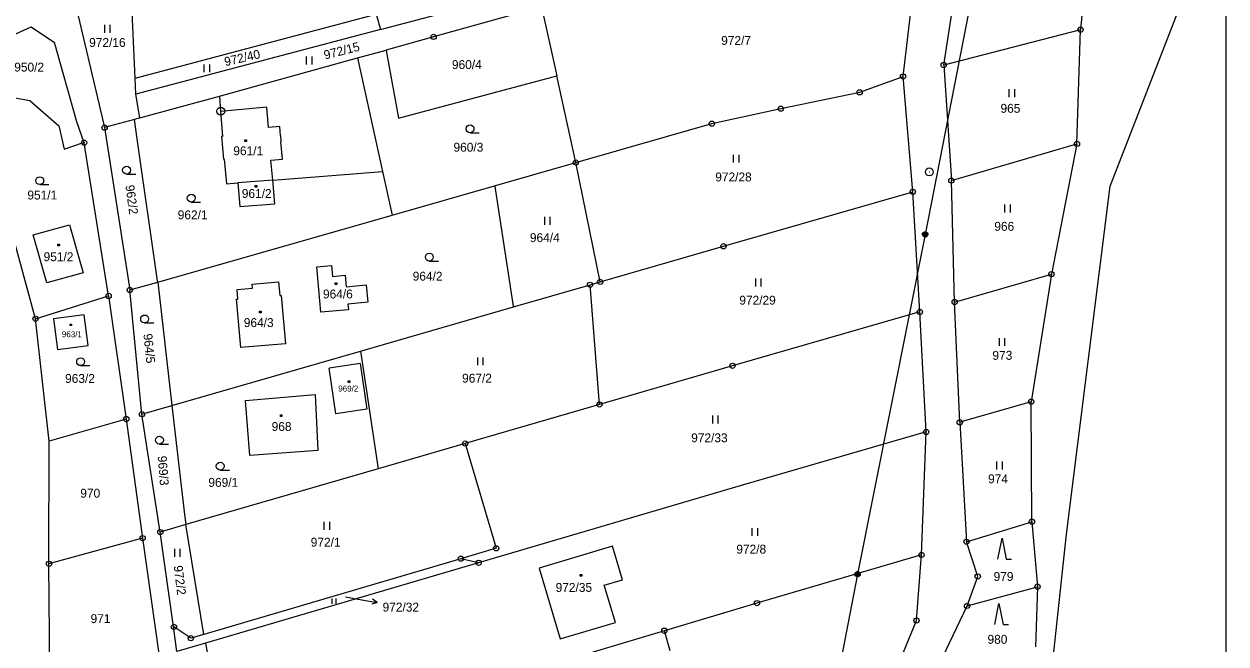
# Model space of a CAD drawing. Extents: x -468021 to -466942, y -1130484 to -1128584.
# Drawn here: x -467170.9 to -466941.7, y -1129239.8 to -1129121.4 of the extents above; entities that cross this region are included whole.
import ezdxf

# ---------------------------------------------------------------- set-up
doc = ezdxf.new("R2010")
doc.units = 0
doc.layers.add('Default', color=7, linetype='Continuous')
doc.layers.add('DKM', color=7, linetype='Continuous')

msp = doc.modelspace()

# ---------------------------------------------------------------- linework, layer by layer
at = {"layer": 'Default'}
msp.add_lwpolyline([(-468020.6, -1128583.91), (-466941.68, -1128583.91), (-466941.68, -1130484.41), (-468020.6, -1130484.41)], close=True, dxfattribs=at)
at = {"layer": 'DKM'}
for p, q in [((-466983.71, -1129082.88), (-466999.06, -1129161.56)), ((-466966.57, -1129091.24), (-466969.42, -1129122.46)), ((-466963.77, -1129152.34), (-466941.68, -1129095.42)), ((-467149.75, -1129131.7), (-467150.67, -1129112.24)), ((-467102.98, -1129122.41), (-467066.02, -1129112.62)), ((-467161.67, -1129115.34), (-467155.58, -1129141.16)), ((-467003.28, -1129131.38), (-467001.42, -1129115.84)), ((-467072.22, -1129118.09), (-467092.82, -1129123.83)), ((-467072.22, -1129118.09), (-467069.34, -1129131.24)), ((-466995.53, -1129129.21), (-466993.65, -1129117.29)), ((-467149.75, -1129131.7), (-467103.75, -1129119.52)), ((-467103.75, -1129119.52), (-467102.98, -1129122.41)), ((-467185.23, -1129128.92), (-467169.61, -1129121.93)), ((-467169.61, -1129121.93), (-467165.17, -1129124.91)), ((-467155.57, -1129123.05), (-467155.57, -1129121.55)), ((-467154.57, -1129121.55), (-467154.57, -1129123.05)), ((-467102.98, -1129122.41), (-467149.61, -1129134.77)), ((-466969.42, -1129122.46), (-466995.53, -1129129.21)), ((-466970.1, -1129144.26), (-466969.42, -1129122.46)), ((-467160.88, -1129140.03), (-467165.17, -1129124.91)), ((-467092.82, -1129123.83), (-467101.88, -1129126.34)), ((-467133.69, -1129135.12), (-467107.36, -1129127.85)), ((-467117.06, -1129129.08), (-467117.06, -1129127.58)), ((-467116.06, -1129127.58), (-467116.06, -1129129.08)), ((-467107.36, -1129127.85), (-467101.88, -1129126.34)), ((-467107.36, -1129127.85), (-467102.59, -1129149.55)), ((-467101.88, -1129126.34), (-467101.74, -1129127.13)), ((-467101.74, -1129127.13), (-467099.52, -1129139.34)), ((-467136.57, -1129130.57), (-467136.57, -1129129.07)), ((-467135.57, -1129129.07), (-467135.57, -1129130.57)), ((-466995.53, -1129129.21), (-466994.06, -1129151.26)), ((-467149.61, -1129134.77), (-467149.75, -1129131.7)), ((-467099.52, -1129139.34), (-467069.34, -1129131.24)), ((-467065.71, -1129147.83), (-467069.34, -1129131.24)), ((-467011.55, -1129134.41), (-467003.28, -1129131.38)), ((-467001.42, -1129153.42), (-467003.28, -1129131.38)), ((-467149.05, -1129138.16), (-467149.61, -1129134.77)), ((-467026.6, -1129137.53), (-467011.55, -1129134.41)), ((-466983.02, -1129135.32), (-466983.02, -1129133.82)), ((-466982.02, -1129133.82), (-466982.02, -1129135.32)), ((-467174.46, -1129135.18), (-467169.84, -1129135.98)), ((-467169.84, -1129135.98), (-467164.31, -1129140.84)), ((-467148.86, -1129139.31), (-467133.69, -1129135.12)), ((-467133.69, -1129135.12), (-467133.47, -1129138.05)), ((-467124.64, -1129137.24), (-467133.47, -1129138.05)), ((-467124.32, -1129141.12), (-467124.64, -1129137.24)), ((-467148.86, -1129139.31), (-467149.9, -1129139.59)), ((-467148.86, -1129139.31), (-467149.05, -1129138.16)), ((-467133.47, -1129138.05), (-467133.11, -1129142.83)), ((-467039.75, -1129140.4), (-467026.6, -1129137.53)), ((-467164.31, -1129140.84), (-467163.28, -1129145.25)), ((-467159.49, -1129144.03), (-467160.88, -1129140.03)), ((-467149.9, -1129139.59), (-467155.58, -1129141.16)), ((-467155.58, -1129141.16), (-467150.77, -1129172.16)), ((-467149.37, -1129143.29), (-467149.9, -1129139.59)), ((-467122.18, -1129140.94), (-467124.32, -1129141.12)), ((-467122.03, -1129142.71), (-467122.18, -1129140.94)), ((-467065.71, -1129147.83), (-467039.75, -1129140.4)), ((-467163.28, -1129145.25), (-467159.82, -1129144.08)), ((-467159.82, -1129144.08), (-467159.49, -1129144.03)), ((-467154.81, -1129173.3), (-467159.49, -1129144.03)), ((-467145.48, -1129170.43), (-467149.37, -1129143.29)), ((-467133.11, -1129142.83), (-467133.26, -1129142.84)), ((-467133.26, -1129142.84), (-467132.9, -1129147.17)), ((-467128.81, -1129143.5), (-467128.51, -1129143.5)), ((-467128.81, -1129143.8), (-467128.81, -1129143.5)), ((-467128.51, -1129143.8), (-467128.81, -1129143.8)), ((-467128.51, -1129143.5), (-467128.51, -1129143.8)), ((-467122.03, -1129142.71), (-467121.94, -1129143.85)), ((-467121.66, -1129147.19), (-467121.94, -1129143.85)), ((-467085.87, -1129142.14), (-467084.12, -1129142.14)), ((-467035.61, -1129147.84), (-467035.61, -1129146.34)), ((-467034.61, -1129146.34), (-467034.61, -1129147.84)), ((-466994.06, -1129151.26), (-466970.1, -1129144.26)), ((-466970.1, -1129144.26), (-466974.96, -1129169.14)), ((-467132.9, -1129147.17), (-467132.75, -1129147.16)), ((-467132.75, -1129147.16), (-467132.35, -1129151.91)), ((-467123.86, -1129147.37), (-467121.66, -1129147.19)), ((-467123.52, -1129151.21), (-467123.86, -1129147.37)), ((-467081.19, -1129152.25), (-467065.71, -1129147.83)), ((-467061.06, -1129170.62), (-467065.71, -1129147.83)), ((-467151.39, -1129150.03), (-467149.64, -1129150.03)), ((-467123.52, -1129151.21), (-467102.59, -1129149.55)), ((-467102.59, -1129149.55), (-467100.76, -1129157.85)), ((-467167.96, -1129152.04), (-467166.21, -1129152.04)), ((-467132.35, -1129151.91), (-467130.14, -1129151.73)), ((-467123.52, -1129151.21), (-467130.14, -1129151.73)), ((-467130.14, -1129151.73), (-467129.77, -1129156.25)), ((-467126.84, -1129152.23), (-467126.54, -1129152.23)), ((-467126.84, -1129152.53), (-467126.84, -1129152.23)), ((-467126.54, -1129152.53), (-467126.84, -1129152.53)), ((-467126.54, -1129152.23), (-467126.54, -1129152.53)), ((-467123.13, -1129155.7), (-467123.52, -1129151.21)), ((-467100.76, -1129157.85), (-467081.19, -1129152.25)), ((-467081.19, -1129152.25), (-467081.16, -1129152.42)), ((-467081.16, -1129152.42), (-467077.64, -1129175.22)), ((-466993.44, -1129174.46), (-466994.06, -1129151.26)), ((-466972.08, -1129218.81), (-466963.77, -1129152.34)), ((-467139.06, -1129155.37), (-467137.31, -1129155.37)), ((-467037.52, -1129163.81), (-467001.42, -1129153.42)), ((-467000.07, -1129176.35), (-467001.42, -1129153.42)), ((-467145.46, -1129170.64), (-467100.76, -1129157.85)), ((-467129.77, -1129156.25), (-467123.13, -1129155.7)), ((-466983.87, -1129157.36), (-466983.87, -1129155.86)), ((-466982.87, -1129155.86), (-466982.87, -1129157.36)), ((-467169.21, -1129161.66), (-467162.29, -1129159.75)), ((-467162.29, -1129159.75), (-467159.69, -1129168.87)), ((-467071.64, -1129159.7), (-467071.64, -1129158.2)), ((-467070.64, -1129158.2), (-467070.64, -1129159.7)), ((-467168.75, -1129177.66), (-467173.37, -1129160.77)), ((-467166.63, -1129170.82), (-467169.21, -1129161.66)), ((-466999.06, -1129161.56), (-467011.96, -1129226.44)), ((-466999.56, -1129161.46), (-466999.46, -1129161.26)), ((-466999.56, -1129161.66), (-466999.56, -1129161.46)), ((-466999.46, -1129161.86), (-466999.56, -1129161.66)), ((-466999.46, -1129161.26), (-466999.36, -1129161.16)), ((-466999.36, -1129161.96), (-466999.46, -1129161.86)), ((-466999.36, -1129161.16), (-466999.16, -1129161.06)), ((-466999.36, -1129161.36), (-466999.36, -1129161.76)), ((-466999.36, -1129161.76), (-466999.16, -1129161.86)), ((-466999.16, -1129162.06), (-466999.36, -1129161.96)), ((-466999.16, -1129161.06), (-466998.96, -1129161.06)), ((-466999.16, -1129161.86), (-466999.16, -1129161.26)), ((-466999.16, -1129161.26), (-466998.96, -1129161.26)), ((-466998.96, -1129162.06), (-466999.16, -1129162.06)), ((-466998.96, -1129161.06), (-466998.76, -1129161.16)), ((-466998.96, -1129161.26), (-466998.96, -1129161.86)), ((-466998.96, -1129161.86), (-466998.76, -1129161.76)), ((-466998.76, -1129161.96), (-466998.96, -1129162.06)), ((-466998.76, -1129161.16), (-466998.66, -1129161.26)), ((-466998.76, -1129161.76), (-466998.76, -1129161.36)), ((-466998.66, -1129161.86), (-466998.76, -1129161.96)), ((-466998.66, -1129161.26), (-466998.56, -1129161.46)), ((-466998.56, -1129161.66), (-466998.66, -1129161.86)), ((-466998.56, -1129161.46), (-466998.56, -1129161.66)), ((-467164.48, -1129163.4), (-467164.18, -1129163.4)), ((-467164.48, -1129163.7), (-467164.48, -1129163.4)), ((-467164.18, -1129163.7), (-467164.48, -1129163.7)), ((-467164.18, -1129163.4), (-467164.18, -1129163.7)), ((-467061.06, -1129170.62), (-467037.52, -1129163.81)), ((-467093.64, -1129166.63), (-467091.89, -1129166.63)), ((-467159.69, -1129168.87), (-467166.63, -1129170.82)), ((-467115.11, -1129167.77), (-467112.32, -1129167.51)), ((-467114.31, -1129176.42), (-467115.11, -1129167.77)), ((-467112.32, -1129167.51), (-467112.14, -1129169.56)), ((-467112.14, -1129169.56), (-467109.72, -1129169.34)), ((-467109.72, -1129169.34), (-467109.5, -1129171.57)), ((-466993.44, -1129174.46), (-466974.96, -1129169.14)), ((-466974.96, -1129169.14), (-466978.84, -1129193.5)), ((-467150.77, -1129172.16), (-467145.46, -1129170.64)), ((-467145.46, -1129170.64), (-467145.48, -1129170.43)), ((-467145.46, -1129170.64), (-467142.75, -1129194.24)), ((-467127.45, -1129171.04), (-467122.44, -1129170.6)), ((-467127.38, -1129171.81), (-467127.45, -1129171.04)), ((-467122.44, -1129170.6), (-467122.17, -1129173.22)), ((-467111.6, -1129170.82), (-467111.3, -1129170.82)), ((-467111.6, -1129171.12), (-467111.6, -1129170.82)), ((-467111.3, -1129171.12), (-467111.6, -1129171.12)), ((-467111.3, -1129170.82), (-467111.3, -1129171.12)), ((-467109.5, -1129171.57), (-467105.68, -1129171.18)), ((-467105.68, -1129171.18), (-467105.36, -1129174.51)), ((-467077.61, -1129175.4), (-467062.98, -1129171.17)), ((-467062.98, -1129171.17), (-467061.06, -1129170.62)), ((-467061.17, -1129194.02), (-467062.98, -1129171.17)), ((-467031.39, -1129171.47), (-467031.39, -1129169.97)), ((-467030.39, -1129169.97), (-467030.39, -1129171.47)), ((-467168.75, -1129177.66), (-467154.81, -1129173.3)), ((-467154.81, -1129173.3), (-467151.45, -1129196.81)), ((-467148.45, -1129195.89), (-467150.77, -1129172.16)), ((-467130.44, -1129173.94), (-467130.17, -1129173.92)), ((-467129.57, -1129183.15), (-467130.44, -1129173.94)), ((-467130.27, -1129172.05), (-467127.38, -1129171.81)), ((-467130.17, -1129173.92), (-467130.27, -1129172.05)), ((-467122.17, -1129173.22), (-467121.92, -1129173.2)), ((-467121.92, -1129173.2), (-467121.05, -1129182.46)), ((-467126.02, -1129176.21), (-467125.72, -1129176.21)), ((-467126.02, -1129176.51), (-467126.02, -1129176.21)), ((-467125.72, -1129176.21), (-467125.72, -1129176.51)), ((-467109.07, -1129175.97), (-467114.31, -1129176.42)), ((-467105.36, -1129174.51), (-467109.18, -1129174.88)), ((-467109.18, -1129174.88), (-467109.07, -1129175.97)), ((-467106.76, -1129183.83), (-467077.61, -1129175.4)), ((-467077.64, -1129175.22), (-467077.61, -1129175.4)), ((-466992.47, -1129197.42), (-466993.44, -1129174.46)), ((-467166.17, -1129201), (-467168.75, -1129177.66)), ((-467159.51, -1129176.89), (-467165.35, -1129177.7)), ((-467165.35, -1129177.7), (-467164.55, -1129183.54)), ((-467158.73, -1129182.75), (-467159.51, -1129176.89)), ((-467147.95, -1129178.44), (-467146.2, -1129178.44)), ((-467125.72, -1129176.51), (-467126.02, -1129176.51)), ((-467000.07, -1129176.35), (-467035.82, -1129186.64)), ((-466998.86, -1129199.28), (-467000.07, -1129176.35)), ((-467162.18, -1129178.66), (-467161.88, -1129178.66)), ((-467162.18, -1129178.96), (-467162.18, -1129178.66)), ((-467161.88, -1129178.96), (-467162.18, -1129178.96)), ((-467161.88, -1129178.66), (-467161.88, -1129178.96)), ((-467164.55, -1129183.54), (-467158.73, -1129182.75)), ((-467121.05, -1129182.46), (-467129.57, -1129183.15)), ((-466984.9, -1129182.83), (-466984.9, -1129181.33)), ((-466983.9, -1129181.33), (-466983.9, -1129182.83)), ((-467142.75, -1129194.24), (-467106.76, -1129183.83)), ((-467106.76, -1129183.83), (-467103.42, -1129206.31)), ((-467084.41, -1129186.53), (-467084.41, -1129185.03)), ((-467083.41, -1129185.03), (-467083.41, -1129186.53)), ((-467160.16, -1129186.61), (-467158.41, -1129186.61)), ((-467106.81, -1129186.23), (-467112.75, -1129187.08)), ((-467111.5, -1129195.79), (-467112.75, -1129187.08)), ((-467106.81, -1129186.23), (-467105.56, -1129194.94)), ((-467035.82, -1129186.64), (-467061.17, -1129194.02)), ((-467109.13, -1129189.54), (-467108.83, -1129189.54)), ((-467109.13, -1129189.84), (-467109.13, -1129189.54)), ((-467108.83, -1129189.84), (-467109.13, -1129189.84)), ((-467108.83, -1129189.54), (-467108.83, -1129189.84)), ((-467128.73, -1129193.28), (-467115.42, -1129192.11)), ((-467115.42, -1129192.11), (-467114.89, -1129202.8)), ((-467148.45, -1129195.89), (-467142.75, -1129194.24)), ((-467142.75, -1129194.24), (-467140.37, -1129215.05)), ((-467127.89, -1129203.79), (-467128.73, -1129193.28)), ((-467061.17, -1129194.02), (-467086.8, -1129201.48)), ((-466978.84, -1129193.5), (-466992.47, -1129197.42)), ((-466978.69, -1129216.41), (-466978.84, -1129193.5)), ((-467151.45, -1129196.81), (-467166.17, -1129201)), ((-467151.45, -1129196.81), (-467148.33, -1129219.55)), ((-467144.96, -1129218.4), (-467148.45, -1129195.89)), ((-467122.05, -1129196.01), (-467121.75, -1129196.01)), ((-467122.05, -1129196.31), (-467122.05, -1129196.01)), ((-467121.75, -1129196.31), (-467122.05, -1129196.31)), ((-467121.75, -1129196.01), (-467121.75, -1129196.31)), ((-467105.56, -1129194.94), (-467111.5, -1129195.79)), ((-467039.59, -1129197.66), (-467039.59, -1129196.16)), ((-467038.59, -1129196.16), (-467038.59, -1129197.66)), ((-466992.47, -1129197.42), (-466991.17, -1129220.25)), ((-467166.19, -1129224.44), (-467166.17, -1129201)), ((-466998.86, -1129199.28), (-467033.73, -1129209.36)), ((-466999.75, -1129222.75), (-466998.86, -1129199.28)), ((-467145.12, -1129201.59), (-467143.37, -1129201.59)), ((-467114.89, -1129202.8), (-467127.89, -1129203.79)), ((-467086.8, -1129201.48), (-467103.42, -1129206.31)), ((-467086.8, -1129201.48), (-467080.89, -1129221.49)), ((-466985.4, -1129206.41), (-466985.4, -1129204.91)), ((-466984.4, -1129204.91), (-466984.4, -1129206.41)), ((-467103.42, -1129206.31), (-467140.06, -1129216.97)), ((-467133.53, -1129206.56), (-467131.78, -1129206.56)), ((-467033.73, -1129209.36), (-467084.23, -1129224.25)), ((-467140.37, -1129215.05), (-467140.06, -1129216.97)), ((-467140.06, -1129216.97), (-467144.96, -1129218.4)), ((-467136.63, -1129237.92), (-467140.06, -1129216.97)), ((-467113.69, -1129217.94), (-467113.69, -1129216.44)), ((-467112.69, -1129216.44), (-467112.69, -1129217.94)), ((-466991.17, -1129220.25), (-466978.69, -1129216.41)), ((-466978.69, -1129216.41), (-466977.62, -1129228.82)), ((-467148.33, -1129219.55), (-467166.19, -1129224.44)), ((-467148.33, -1129219.55), (-467145.18, -1129242.09)), ((-467142.45, -1129236.44), (-467144.96, -1129218.4)), ((-467032.03, -1129219.13), (-467032.03, -1129217.63)), ((-467031.03, -1129217.63), (-467031.03, -1129219.13)), ((-466985.2, -1129223.57), (-466984.4, -1129219.57)), ((-466984.4, -1129219.57), (-466983.6, -1129223.57)), ((-466975.58, -1129251.34), (-466972.08, -1129218.81)), ((-467142.21, -1129223.12), (-467142.21, -1129221.62)), ((-467141.21, -1129221.62), (-467141.21, -1129223.12)), ((-467080.89, -1129221.49), (-467087.61, -1129223.47)), ((-467058.67, -1129221.11), (-467072.67, -1129225.28)), ((-467056.77, -1129227.49), (-467058.67, -1129221.11)), ((-466989.03, -1129226.87), (-466991.17, -1129220.25)), ((-467087.61, -1129223.47), (-467136.63, -1129237.92)), ((-467084.23, -1129224.25), (-467136.35, -1129239.61)), ((-467084.23, -1129224.25), (-467087.61, -1129223.47)), ((-466999.75, -1129222.75), (-467031.15, -1129231.95)), ((-467000.72, -1129235.28), (-466999.75, -1129222.75)), ((-466983.6, -1129223.57), (-466982.6, -1129223.57)), ((-467166.01, -1129248.11), (-467166.19, -1129224.44)), ((-467072.67, -1129225.28), (-467068.67, -1129238.8)), ((-467064.85, -1129226.51), (-467064.55, -1129226.51)), ((-467064.85, -1129226.81), (-467064.85, -1129226.51)), ((-467064.55, -1129226.51), (-467064.55, -1129226.81)), ((-467011.96, -1129226.44), (-467026.85, -1129303.88)), ((-467012.46, -1129226.34), (-467012.36, -1129226.14)), ((-467012.46, -1129226.54), (-467012.46, -1129226.34)), ((-467012.36, -1129226.74), (-467012.46, -1129226.54)), ((-467012.36, -1129226.14), (-467012.26, -1129226.04)), ((-467012.26, -1129226.04), (-467012.06, -1129225.94)), ((-467012.26, -1129226.24), (-467012.26, -1129226.64)), ((-467012.26, -1129226.64), (-467012.06, -1129226.74)), ((-467012.06, -1129225.94), (-467011.86, -1129225.94)), ((-467012.06, -1129226.74), (-467012.06, -1129226.14)), ((-467012.06, -1129226.14), (-467011.86, -1129226.14)), ((-467011.86, -1129225.94), (-467011.66, -1129226.04)), ((-467011.86, -1129226.14), (-467011.86, -1129226.74)), ((-467011.86, -1129226.74), (-467011.66, -1129226.64)), ((-467011.66, -1129226.04), (-467011.56, -1129226.14)), ((-467011.66, -1129226.64), (-467011.66, -1129226.24)), ((-467011.56, -1129226.14), (-467011.46, -1129226.34)), ((-467011.46, -1129226.54), (-467011.56, -1129226.74)), ((-467011.46, -1129226.34), (-467011.46, -1129226.54)), ((-467064.55, -1129226.81), (-467064.85, -1129226.81)), ((-467060.26, -1129228.52), (-467056.77, -1129227.49)), ((-467058.14, -1129235.69), (-467060.26, -1129228.52)), ((-467012.26, -1129226.84), (-467012.36, -1129226.74)), ((-467012.06, -1129226.94), (-467012.26, -1129226.84)), ((-467011.86, -1129226.94), (-467012.06, -1129226.94)), ((-467011.66, -1129226.84), (-467011.86, -1129226.94)), ((-467011.56, -1129226.74), (-467011.66, -1129226.84)), ((-466991.07, -1129232.49), (-466989.03, -1129226.87)), ((-466991.07, -1129232.49), (-466977.62, -1129228.82)), ((-466977.62, -1129228.82), (-466978.04, -1129240.28)), ((-467112.15, -1129232.09), (-467112.15, -1129231.08)), ((-467111.48, -1129231.08), (-467111.48, -1129232.09)), ((-467109.6, -1129230.75), (-467106.51, -1129231.32)), ((-467103.56, -1129231.87), (-467104.45, -1129231.19)), ((-467106.51, -1129231.32), (-467103.56, -1129231.87)), ((-467103.56, -1129231.87), (-467104.63, -1129232.18)), ((-467031.15, -1129231.95), (-467048.81, -1129237.23)), ((-466997.42, -1129245.79), (-466991.07, -1129232.49)), ((-466985.78, -1129236.03), (-466984.98, -1129232.03)), ((-466984.98, -1129232.03), (-466984.18, -1129236.03)), ((-467068.67, -1129238.8), (-467058.14, -1129235.69)), ((-467006.12, -1129248.46), (-467000.72, -1129235.28)), ((-467141.78, -1129241.21), (-467142.45, -1129236.44)), ((-467142.45, -1129236.44), (-467142.36, -1129236.5)), ((-467139.14, -1129238.66), (-467142.36, -1129236.5)), ((-467136.63, -1129237.92), (-467139.14, -1129238.66)), ((-467048.81, -1129237.23), (-467132.13, -1129262.11)), ((-467047.69, -1129241.07), (-467048.81, -1129237.23)), ((-466984.18, -1129236.03), (-466983.18, -1129236.03)), ((-467136.35, -1129239.61), (-467141.78, -1129241.21)), ((-467136.35, -1129239.61), (-467132.13, -1129262.11))]:
    msp.add_line(p, q, dxfattribs=at)
for centre, radius in [((-467092.82, -1129123.83), 0.5), ((-466969.42, -1129122.46), 0.5), ((-466969.42, -1129122.46), 0.01), ((-467092.82, -1129123.83), 0.01), ((-466995.53, -1129129.21), 0.5), ((-466995.53, -1129129.21), 0.01), ((-467003.28, -1129131.38), 0.5), ((-467003.28, -1129131.38), 0.01), ((-467011.55, -1129134.41), 0.5), ((-467011.55, -1129134.41), 0.01), ((-467133.43, -1129138.02), 0.75), ((-467026.6, -1129137.53), 0.5), ((-467133.43, -1129138.02), 0.01), ((-467026.6, -1129137.53), 0.01), ((-467155.58, -1129141.16), 0.5), ((-467155.58, -1129141.16), 0.01), ((-467085.87, -1129141.39), 0.75), ((-467039.75, -1129140.4), 0.5), ((-467039.75, -1129140.4), 0.01), ((-467159.49, -1129144.03), 0.5), ((-467159.49, -1129144.03), 0.01), ((-466970.1, -1129144.26), 0.5), ((-466970.1, -1129144.26), 0.01), ((-467151.39, -1129149.28), 0.75), ((-467065.71, -1129147.83), 0.5), ((-467065.71, -1129147.83), 0.01), ((-467167.96, -1129151.29), 0.75), ((-466998.26, -1129149.61), 0.75), ((-466998.26, -1129149.61), 0.01), ((-466994.06, -1129151.26), 0.5), ((-467001.42, -1129153.42), 0.5), ((-466994.06, -1129151.26), 0.01), ((-467139.06, -1129154.62), 0.75), ((-467001.42, -1129153.42), 0.01), ((-467037.52, -1129163.81), 0.5), ((-467037.52, -1129163.81), 0.01), ((-467093.64, -1129165.88), 0.75), ((-466974.96, -1129169.14), 0.5), ((-466974.96, -1129169.14), 0.01), ((-467150.77, -1129172.16), 0.5), ((-467062.98, -1129171.17), 0.5), ((-467062.98, -1129171.17), 0.01), ((-467061.06, -1129170.62), 0.5), ((-467061.06, -1129170.62), 0.01), ((-467154.81, -1129173.3), 0.5), ((-467154.81, -1129173.3), 0.01), ((-467150.77, -1129172.16), 0.01), ((-467000.07, -1129176.35), 0.5), ((-466993.44, -1129174.46), 0.5), ((-466993.44, -1129174.46), 0.01), ((-467168.75, -1129177.66), 0.5), ((-467168.75, -1129177.66), 0.01), ((-467147.95, -1129177.69), 0.75), ((-467000.07, -1129176.35), 0.01), ((-467160.16, -1129185.86), 0.75), ((-467035.82, -1129186.64), 0.5), ((-467035.82, -1129186.64), 0.01), ((-467061.17, -1129194.02), 0.5), ((-467061.17, -1129194.02), 0.01), ((-466978.84, -1129193.5), 0.5), ((-466978.84, -1129193.5), 0.01), ((-467151.45, -1129196.81), 0.5), ((-467151.45, -1129196.81), 0.01), ((-467148.45, -1129195.89), 0.5), ((-467148.45, -1129195.89), 0.01), ((-466998.86, -1129199.28), 0.5), ((-466992.47, -1129197.42), 0.5), ((-466992.47, -1129197.42), 0.01), ((-467145.12, -1129200.84), 0.75), ((-467086.8, -1129201.48), 0.5), ((-466998.86, -1129199.28), 0.01), ((-467086.8, -1129201.48), 0.01), ((-467133.53, -1129205.81), 0.75), ((-466978.69, -1129216.41), 0.5), ((-466978.69, -1129216.41), 0.01), ((-467148.33, -1129219.55), 0.5), ((-467148.33, -1129219.55), 0.01), ((-467144.96, -1129218.4), 0.5), ((-467144.96, -1129218.4), 0.01), ((-466991.17, -1129220.25), 0.5), ((-467080.89, -1129221.49), 0.5), ((-467080.89, -1129221.49), 0.01), ((-466991.17, -1129220.25), 0.01), ((-467166.19, -1129224.44), 0.5), ((-467087.61, -1129223.47), 0.5), ((-467087.61, -1129223.47), 0.01), ((-467084.23, -1129224.25), 0.5), ((-467084.23, -1129224.25), 0.01), ((-466999.75, -1129222.75), 0.5), ((-466999.75, -1129222.75), 0.01), ((-467166.19, -1129224.44), 0.01), ((-466989.03, -1129226.87), 0.5), ((-466989.03, -1129226.87), 0.01), ((-466977.62, -1129228.82), 0.5), ((-466977.62, -1129228.82), 0.01), ((-467031.15, -1129231.95), 0.5), ((-467031.15, -1129231.95), 0.01), ((-466991.07, -1129232.49), 0.5), ((-466991.07, -1129232.49), 0.01), ((-467000.72, -1129235.28), 0.5), ((-467000.72, -1129235.28), 0.01), ((-467142.36, -1129236.5), 0.5), ((-467142.36, -1129236.5), 0.01), ((-467048.81, -1129237.23), 0.5), ((-467048.81, -1129237.23), 0.01), ((-467139.14, -1129238.66), 0.5), ((-467139.14, -1129238.66), 0.01)]:
    msp.add_circle(centre, radius, dxfattribs=at)

# ---------------------------------------------------------------- texts
for s, height, p in [('972/16', 1.7, (-467158.53, -1129125.75)), ('972/7', 1.7, (-467037.97, -1129125.36)), ('950/2', 1.7, (-467172.82, -1129130.45)), ('960/4', 1.7, (-467089.33, -1129129.97)), ('965', 1.7, (-466984.69, -1129138.32)), ('960/3', 1.7, (-467089.03, -1129145.75)), ('961/1', 1.7, (-467131.03, -1129146.43)), ('972/28', 1.7, (-467039.1, -1129151.43)), ('951/1', 1.7, (-467170.31, -1129154.88)), ('961/2', 1.7, (-467129.41, -1129154.58)), ('962/1', 1.7, (-467141.63, -1129158.66)), ('966', 1.7, (-466985.87, -1129160.86)), ('964/4', 1.7, (-467074.46, -1129163.02)), ('951/2', 1.7, (-467167.22, -1129166.66)), ('964/2', 1.7, (-467096.81, -1129170.38)), ('964/6', 1.7, (-467113.93, -1129173.78)), ('972/29', 1.7, (-467034.51, -1129174.96)), ('964/3', 1.7, (-467129.03, -1129179.24)), ('963/1', 1.14, (-467163.73, -1129181.18)), ('973', 1.7, (-466986.23, -1129185.49)), ('963/2', 1.7, (-467163.12, -1129189.91)), ('967/2', 1.7, (-467087.39, -1129189.85)), ('969/2', 1.14, (-467111.01, -1129191.56)), ('968', 1.7, (-467123.72, -1129199.08)), ('972/33', 1.7, (-467043.69, -1129201.24)), ('969/1', 1.7, (-467135.79, -1129209.75)), ('974', 1.7, (-466987.06, -1129209.07)), ('970', 1.7, (-467160.22, -1129211.82)), ('972/1', 1.7, (-467116.26, -1129221.18)), ('972/8', 1.7, (-467035.08, -1129222.5)), ('979', 1.7, (-466986.01, -1129227.72)), ('972/35', 1.7, (-467069.55, -1129229.81)), ('972/32', 0.1, (-467109.6, -1129230.75)), ('972/32', 1.7, (-467102.56, -1129233.57)), ('971', 1.7, (-467158.26, -1129235.77)), ('980', 1.7, (-466987.17, -1129239.72))]:
    msp.add_text(s, height=height, dxfattribs=at).set_placement(p)
for s, rotation, p in [('972/15', 14.5564, (-467113.52, -1129128.17)), ('972/40', 13.0097, (-467132.54, -1129129.44)), ('962/2', 277.6577, (-467151.62, -1129152.21)), ('964/5', 275.9468, (-467148.2, -1129180.58)), ('969/3', 274.5574, (-467145.46, -1129203.89)), ('972/2', 277.125, (-467142.42, -1129224.87))]:
    msp.add_text(s, height=1.7, rotation=rotation, dxfattribs=at).set_placement(p)

doc.saveas('drawing.dxf')
